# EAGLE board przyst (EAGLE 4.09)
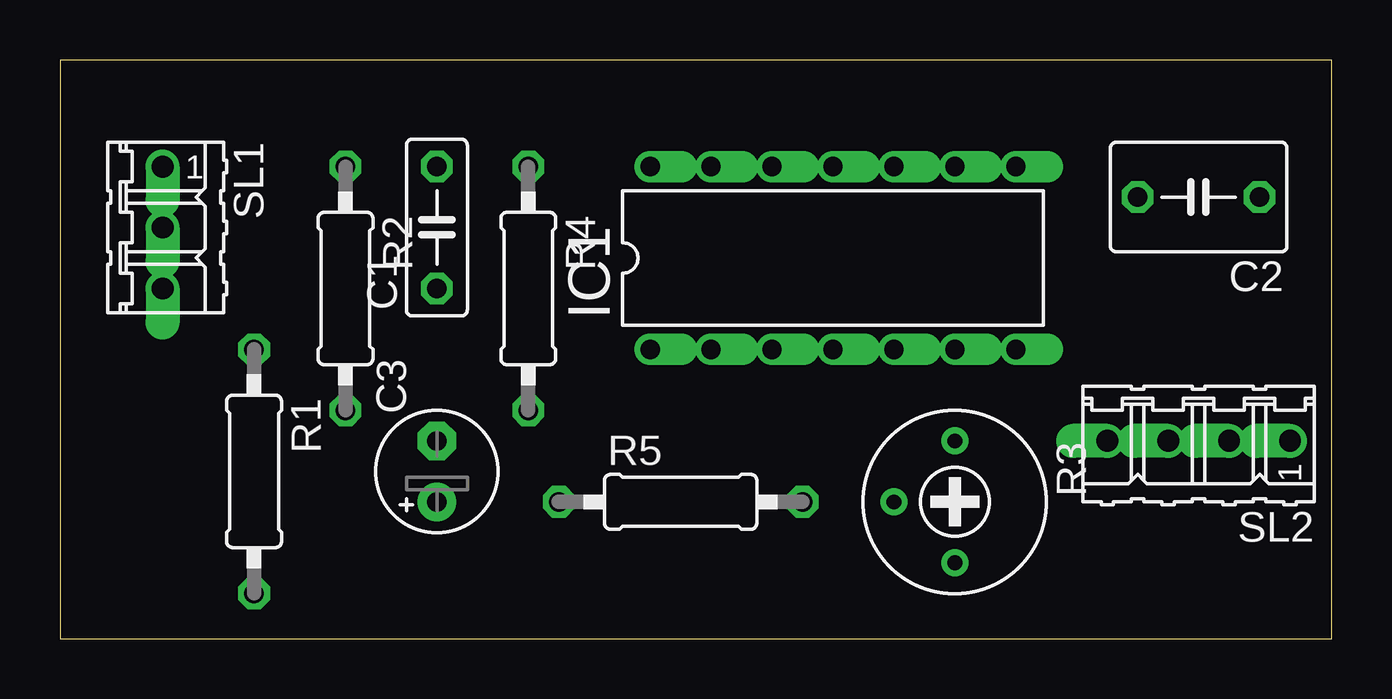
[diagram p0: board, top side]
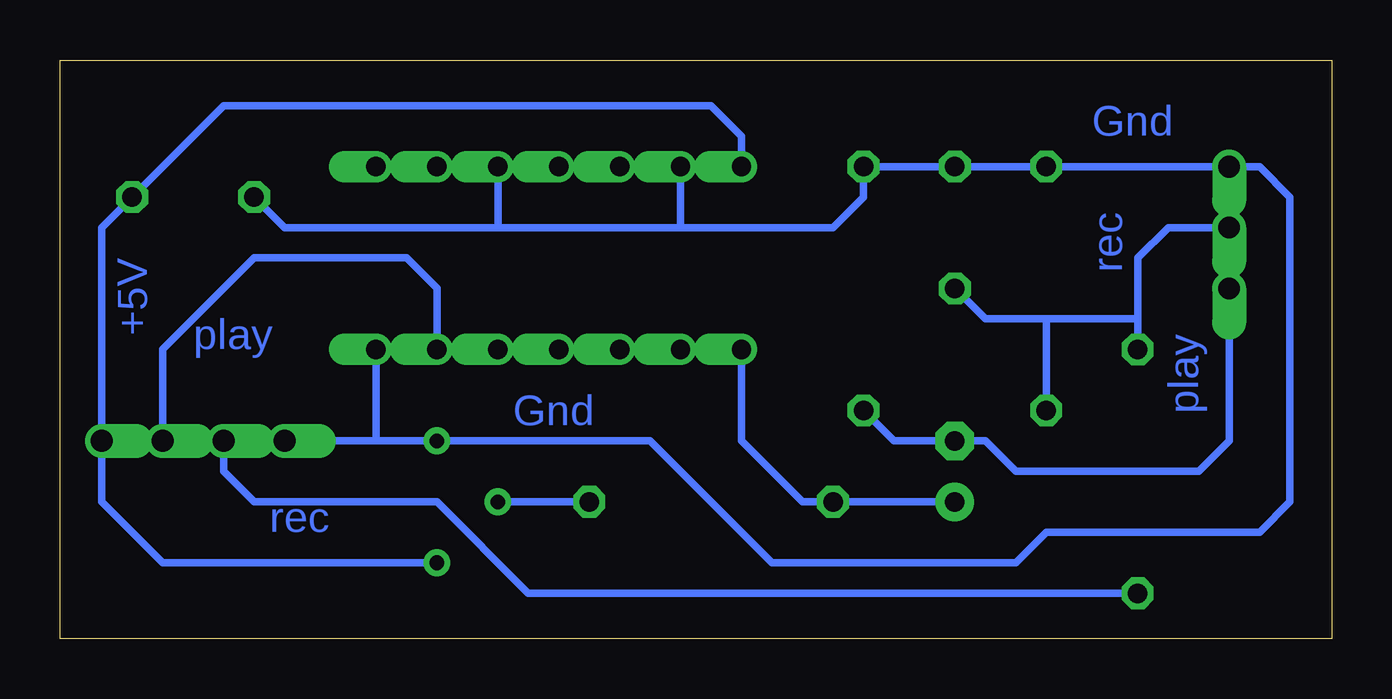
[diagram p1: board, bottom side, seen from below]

Size 53.01 x 24.12 mm. Coordinates in mm from the lower left corner, seen from the top.
Outline: 0,0 53.01,0 53.01,24.12 0,24.12 0,0
Copper layers used: Bottom

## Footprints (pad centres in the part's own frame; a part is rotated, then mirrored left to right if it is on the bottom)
C050-025X075 = drill 0.813 octagon: 1 -2.54,0; 2 2.54,0
C050-045X075 = drill 0.813 octagon: 1 -2.54,0; 2 2.54,0
E2,5-5 = drill 0.813 pad 1.6 round: + -1.27,0 | drill 0.813 pad 1.6 octagon: - 1.27,0
DIL14 = drill 0.8 offset: 1 -7.62,-3.81; 2 -5.08,-3.81; 3 -2.54,-3.81; 4 0,-3.81; 5 2.54,-3.81; 6 5.08,-3.81; 7 7.62,-3.81; 8 7.62,3.81; 9 5.08,3.81; 10 2.54,3.81; 11 0,3.81; 12 -2.54,3.81; 13 -5.08,3.81; 14 -7.62,3.81
0207/10 = drill 0.813 octagon: 1 -5.08,0; 2 5.08,0
RTRIM3339P = drill 0.61 round: 1 -2.54,0; 2 0,-2.54; 3 2.54,0
03P = drill 0.914 offset: 1 -2.54,0; 2 0,0; 3 2.54,0
04P = drill 0.914 offset: 1 -3.81,0; 2 -1.27,0; 3 1.27,0; 4 3.81,0

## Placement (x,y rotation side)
C1  [C050-025X075]  15.71,17.14 90 top
C2  [C050-045X075]  47.46,18.41 180 top
C3  [E2,5-5]  15.71,6.98 90 top
IC1  74HCT132N  [DIL14]  32.22,15.87 0 top
R1  [0207/10]  8.09,6.98 270 top
R2  [0207/10]  11.9,14.6 270 top
R3  [RTRIM3339P]  37.3,5.71 270 top
R4  [0207/10]  19.52,14.6 270 top
R5  [0207/10]  25.87,5.71 0 top
SL1  [03P]  4.28,17.14 270 top
SL2  [04P]  47.46,8.25 180 top

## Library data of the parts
C1-C3 R1-R5 = rcl
IC1 = 74xx-eu
SL1 SL2 = con-amp-quick

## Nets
GND: C1.2 C2.2 IC1.7 IC1.9 IC1.10 IC1.12 IC1.13 R2.1 R3.1 R4.1 SL1.1 SL2.4
N$4: R1.2 SL2.3
N$5: C3.+ IC1.1 IC1.2 R5.1
N$6: R3.2 R5.2
N$14: IC1.3 IC1.4 IC1.5
N$16: IC1.6 SL2.2
PLAY: C3.- R4.2 SL1.3
REC: C1.1 R1.1 R2.2 SL1.2
VCC: C2.1 IC1.14 R3.3 SL2.1

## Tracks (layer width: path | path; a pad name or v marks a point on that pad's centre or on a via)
GND
  Bottom 0.305: IC1.12 IC1.13 27.14,17.14 | IC1.9 IC1.10 34.76,17.14 | 27.14,17.14 20.79,17.14 19.52,18.41 R4.1 C1.2 R2.1 SL1.1 3.01,19.68 1.74,18.41 1.74,5.71 3.01,4.44 11.9,4.44 13.17,3.17 23.33,3.17 28.41,8.25 R3.1 39.84,8.25 | 27.14,17.14 34.76,17.14 | 34.76,17.14 43.65,17.14 C2.2 | 39.84,8.25 SL2.4 | 39.84,8.25 IC1.7
N$4
  Bottom 0.305: R1.2 33.49,1.9 37.3,5.71 44.92,5.71 46.19,6.98 SL2.3
N$5
  Bottom 0.305: IC1.2 IC1.1 24.6,8.25 22.06,5.71 R5.1 C3.+
N$6
  Bottom 0.305: R5.2 R3.2
N$14
  Bottom 0.305: IC1.3 IC1.4 IC1.5
N$16
  Bottom 0.305: IC1.6 37.3,14.6 38.57,15.87 44.92,15.87 48.73,12.06 SL2.2
PLAY
  Bottom 0.305: R4.2 18.25,8.25 C3.- 14.44,8.25 13.17,6.98 5.55,6.98 4.28,8.25 SL1.3
REC
  Bottom 0.305: SL1.2 6.82,17.14 8.09,15.87 8.09,13.33 | 8.09,13.33 R1.1 | R2.2 11.9,13.33 | 11.9,13.33 14.44,13.33 C1.1 | 11.9,13.33 8.09,13.33
VCC
  Bottom 0.305: IC1.14 24.6,20.95 25.87,22.22 46.19,22.22 C2.1 51.27,17.14 SL2.1 51.27,5.71 48.73,3.17 R3.3

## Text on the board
Bottom: Gnd | rec | +5V | play | play | Gnd | rec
